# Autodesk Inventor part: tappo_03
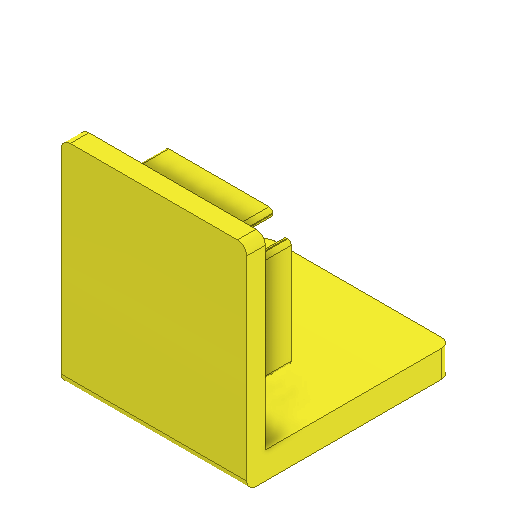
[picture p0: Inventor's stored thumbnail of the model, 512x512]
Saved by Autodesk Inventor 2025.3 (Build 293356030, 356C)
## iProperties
Created: 2026-02
Part Number: tappo_03
Material: Generico
Document SubType Name: Modeling
Designer: R5800u
Density: 1 g/cm^3
Appearance: Giallo canarino
Author: R5800u
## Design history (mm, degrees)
sketch "Schizzo1"
  geometry: L1 (10, 10)-(-10, 10); L2 (-10, 10)-(-10, -10); L3 (-10, -10)-(10, -10); L4 (10, -10)-(10, 10); L5 (10, 10)-(-10, -10); L6 (-10, 10)-(10, -10); L7 (6, -8)-(3, -8) reference; L8 (6, -7.061)-(6, -8) reference; L9 (2.939, -4)-(6, -7.061) reference; L10 (0, 0)-(0, -10); L11 (2.939, -4)-(0, -4); L12 (3, -8)-(0, -8); L13 (0, -7.8)-(3, -7.8); L14 (3, -7.8)-(5.8, -7.8); L15 (5.8, -7.8)-(5.8, -7.144); L16 (5.8, -7.144)-(2.856, -4.2); L17 (2.856, -4.2)-(0, -4.2); L18 (0, -7.8)-(-3, -7.8); L19 (-3, -7.8)-(-5.8, -7.8); L20 (-5.8, -7.8)-(-5.8, -7.144); L21 (-5.8, -7.144)-(-2.856, -4.2); L22 (-2.856, -4.2)-(0, -4.2)
  constraints: 38 end point, 4 symmetric about line, 3 midpoint, 3 perpendicular, 2 parallel, 2 point on line, 1 horizontal, 4 other
  dimensions: "d0" = 20 distance of L3.end L2.end; "d1" = 20 distance of L2.end L1.end; "d2" = 0.2 distance between parallel lines of L12 L13
  node "Riferimento1"
  node "Riferimento2"
  node "Riferimento3"
extrude "Estrusione1" new body sketch "Schizzo1" distance "d3" = 2; taper "d4" = 0 deg
extrude "Estrusione2" new body sketch "Schizzo1" distance "d5" = 1.9; taper "d6" = 0 deg; dims "d11" = 5, "d12" = 0
pattern_circular "Serie circolare1" dims angle "d8" = 360 deg
fillet "Raccordo2" dims "d13" = 0.4
sketch "Schizzo2"
  geometry: 1 further point
hole "Foro1" sketch "Schizzo2" at (0, 0) diameter "d14" = 4.3; stored, may be unused: countersink angle "d18" = 90 deg, drill point angle "d20" = 118 deg; dims "d15" = 6, "d16" = 8, "d17" = 4.6, "d19" = 8
fillet "Raccordo3" dims "d21" = 1
sketch "Schizzo3"
  geometry: L1 (0, 0)-(20, 0) reference; L2 (20, 0)-(20, 2) reference; L3 (0, 2)-(20, 2) reference; L4 (0, 0)-(0, 2) reference; 1 further point
extrude "Estrusione3" join sketch "Schizzo3" distance "d22" = 3; taper "d23" = 0 deg
sketch "Schizzo4"
  geometry: L1 (-10, -13)-(10, -13) reference; L2 (-10, 9)-(-10, -13) reference; L3 (10, -13)-(-10, -13); L4 (-10, -13)-(-10, -10.1); L5 (-10, -10.1)-(10, -10.1); L6 (10, -10.1)-(10, -13); 1 further point
  constraints: 8 end point, 2 parallel, 1 horizontal, 1 perpendicular, 1 point on line
  dimensions: "d24" = 2.9 distance of L3.end L4.end
extrude "Estrusione4" join sketch "Schizzo4" distance "d25" = 20; taper "d26" = 0 deg
fillet "Raccordo4" dims "d27" = 1
node "Solido1"
node "Solido2"
node "Linea chiusa proiettata1"
